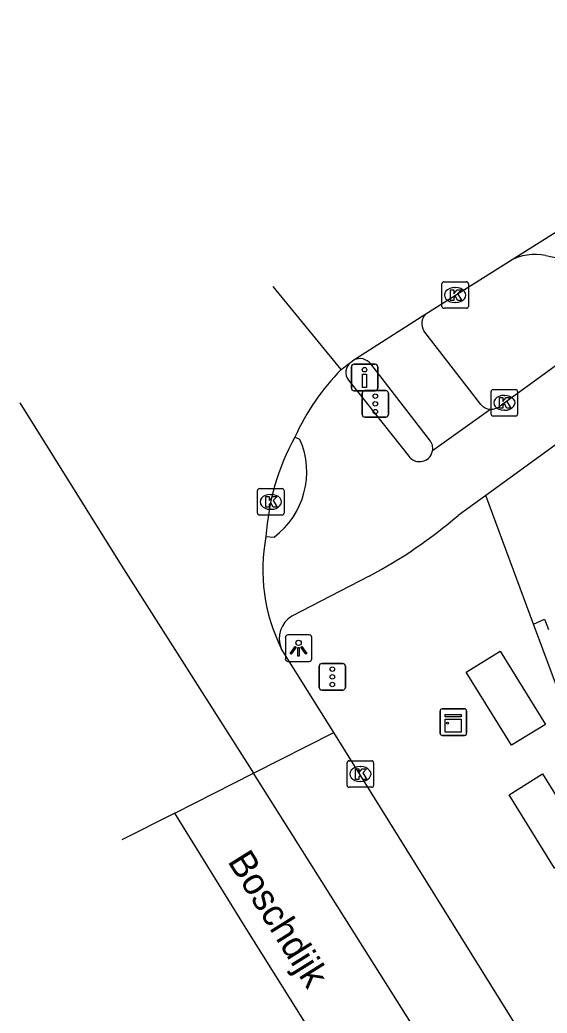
# Model space of a CAD drawing. Extents: x 160806 to 161707, y 383697 to 384148.
# Drawn here: x 160897.89 to 160917.75, y 383917.33 to 383954.76 of the extents above; entities that cross this region are included whole.
import ezdxf

# ---------------------------------------------------------------- set-up
doc = ezdxf.new("R2010")
doc.units = 0
for name, color, linetype in [('IMGEO_Drukknoppaal', 7, 'Continuous'), ('IMGEO_Fietspad_open', 7, 'Continuous'), ('IMGEO_Kast', 7, 'Continuous'), ('IMGEO_Kolk', 7, 'Continuous'), ('IMGEO_Lichtpunt', 7, 'Continuous'), ('IMGEO_Muur', 7, 'Continuous'), ('IMGEO_Openbare_ruimte_label', 7, 'Continuous'), ('IMGEO_Parkeervlak_open', 7, 'Continuous'), ('IMGEO_Rijbaan_lokaal_gesloten', 7, 'Continuous'), ('IMGEO_Rijbaan_lokaal_open', 7, 'Continuous'), ('IMGEO_Verkeersregelinstallatiepaal', 7, 'Continuous'), ('IMGEO_Voetpad_open', 7, 'Continuous')]:
    doc.layers.add(name, color=color, linetype=linetype)

msp = doc.modelspace()

# ---------------------------------------------------------------- linework, layer by layer
at = {"layer": 'IMGEO_Drukknoppaal'}
for p, q in [((160910.376, 383940.887), (160910.376, 383941.687)), ((160910.376, 383941.687), (160910.376, 383940.887)), ((160910.476, 383941.787), (160911.266, 383941.787)), ((160911.266, 383941.787), (160910.476, 383941.787)), ((160911.366, 383941.687), (160911.366, 383940.887)), ((160911.366, 383940.887), (160911.366, 383941.687)), ((160911.266, 383940.787), (160910.476, 383940.787)), ((160910.476, 383940.787), (160911.266, 383940.787))]:
    msp.add_line(p, q, dxfattribs=at)
msp.add_lwpolyline([(160910.946, 383941.412), (160910.946, 383940.912), (160910.796, 383940.912), (160910.796, 383941.412), (160910.946, 383941.412)], dxfattribs=at)
msp.add_circle((160910.871, 383941.577), 0.085, dxfattribs=at)
for centre, start, end in [((160910.476, 383941.687), 90, 180), ((160910.476, 383941.687), 90, 180), ((160911.266, 383941.687), 0, 90), ((160911.266, 383941.687), 360, 90), ((160910.476, 383940.887), 180, 270), ((160910.476, 383940.887), 180, 270), ((160911.266, 383940.887), 270, 0), ((160911.266, 383940.887), 270, 0)]:
    msp.add_arc(centre, 0.1, start, end, dxfattribs=at)
at = {"layer": 'IMGEO_Fietspad_open'}
for points in [[(160930.868, 383948.143), (160928.691, 383946.466), (160915.435, 383936.839)], [(160921.489, 383944.216), (160915.944, 383940.183)], [(160910.264, 383941.18), (160912.535, 383938.326)], [(160915.627, 383940.088), (160913.432, 383938.517)], [(160908.436, 383938.952), (160908.246, 383939.039)], [(160915.435, 383936.839), (160914.394, 383936.084)], [(160907.157, 383935.291), (160907.466, 383935.27)], [(160911.047, 383933.797), (160908.137, 383932.288)]]:
    msp.add_lwpolyline(points, dxfattribs=at)
for centre, radius, start, end in [((160910.656, 383941.475), 0.491, 128.8757, 216.9784), ((160915.641, 383940.616), 0.528, 268.4309, 304.9344), ((160905.618, 383937.726), 3.073, 306.9626, 23.5196), ((160912.945, 383938.61), 0.495, 313.4444, 349.2145), ((160912.943, 383938.609), 0.497, 214.7488, 313.6941), ((160902.215, 383950.316), 18.732, 298.1328, 310.5567), ((160908.632, 383931.451), 0.973, 120.6113, 202.7173)]:
    msp.add_arc(centre, radius, start, end, dxfattribs=at)
at = {"layer": 'IMGEO_Kast'}
for p, q in [((160913.79, 383928.797), (160914.631, 383928.797)), ((160914.631, 383928.797), (160913.79, 383928.797)), ((160913.715, 383927.872), (160913.715, 383928.713)), ((160913.715, 383928.713), (160913.715, 383927.872)), ((160914.715, 383928.722), (160914.715, 383927.881)), ((160914.715, 383927.881), (160914.715, 383928.722)), ((160914.64, 383927.797), (160913.799, 383927.797)), ((160913.799, 383927.797), (160914.64, 383927.797))]:
    msp.add_line(p, q, dxfattribs=at)
for points in [[(160913.91, 383928.587), (160914.51, 383928.587), (160914.51, 383928.502), (160913.91, 383928.502), (160913.91, 383928.587)], [(160913.91, 383928.412), (160914.51, 383928.412), (160914.51, 383927.923), (160913.91, 383927.923), (160913.91, 383928.412)]]:
    msp.add_lwpolyline(points, dxfattribs=at)
msp.add_circle((160913.994, 383928.261), 0.0377, dxfattribs=at)
for centre, start, end in [((160913.793, 383928.719), 92.4484, 184.2845), ((160913.793, 383928.719), 92.4484, 184.2845), ((160914.637, 383928.719), 2.4484, 94.2845), ((160914.637, 383928.719), 2.4484, 94.2845), ((160913.793, 383927.875), 182.4484, 274.2845), ((160913.793, 383927.875), 182.4484, 274.2845), ((160914.637, 383927.875), 272.4484, 4.2845), ((160914.637, 383927.875), 272.4484, 4.2845)]:
    msp.add_arc(centre, 0.0779, start, end, dxfattribs=at)
at = {"layer": 'IMGEO_Kolk'}
for p, q in [((160913.86, 383944.892), (160914.712, 383944.892)), ((160913.785, 383943.966), (160913.785, 383944.818)), ((160914.273, 383944.672), (160914.298, 383944.672)), ((160914.786, 383944.818), (160914.786, 383943.966)), ((160914.712, 383943.892), (160913.86, 383943.892)), ((160914.296, 383944.112), (160914.271, 383944.112)), ((160915.712, 383940.83), (160916.564, 383940.83)), ((160915.637, 383939.904), (160915.637, 383940.756)), ((160916.125, 383940.61), (160916.15, 383940.61)), ((160916.638, 383940.756), (160916.638, 383939.904)), ((160916.148, 383940.05), (160916.123, 383940.05)), ((160916.564, 383939.83), (160915.712, 383939.83)), ((160906.836, 383936.171), (160906.836, 383937.023)), ((160906.911, 383937.097), (160907.763, 383937.097)), ((160907.837, 383937.023), (160907.837, 383936.171)), ((160907.324, 383936.877), (160907.349, 383936.877)), ((160907.347, 383936.317), (160907.322, 383936.317)), ((160907.763, 383936.097), (160906.911, 383936.097)), ((160910.212, 383925.914), (160910.212, 383926.766)), ((160910.287, 383926.84), (160911.139, 383926.84)), ((160910.7, 383926.62), (160910.725, 383926.62)), ((160911.213, 383926.766), (160911.213, 383925.914)), ((160911.139, 383925.84), (160910.287, 383925.84)), ((160910.723, 383926.06), (160910.698, 383926.06))]:
    msp.add_line(p, q, dxfattribs=at)
for points in [[(160913.86, 383944.892), (160914.712, 383944.892)], [(160913.785, 383943.966), (160913.785, 383944.818)], [(160914.106, 383944.592), (160914.229, 383944.592), (160914.229, 383944.441), (160914.359, 383944.592), (160914.523, 383944.592), (160914.377, 383944.441), (160914.53, 383944.192), (160914.378, 383944.192), (160914.293, 383944.356), (160914.229, 383944.289), (160914.229, 383944.192), (160914.106, 383944.192), (160914.106, 383944.592)], [(160914.786, 383944.818), (160914.786, 383943.966)], [(160914.712, 383943.892), (160913.86, 383943.892)], [(160915.712, 383940.83), (160916.564, 383940.83)], [(160915.637, 383939.904), (160915.637, 383940.756)], [(160915.958, 383940.53), (160916.081, 383940.53), (160916.081, 383940.379), (160916.211, 383940.53), (160916.375, 383940.53), (160916.229, 383940.379), (160916.382, 383940.13), (160916.23, 383940.13), (160916.145, 383940.294), (160916.081, 383940.227), (160916.081, 383940.13), (160915.958, 383940.13), (160915.958, 383940.53)], [(160916.638, 383940.756), (160916.638, 383939.904)], [(160916.564, 383939.83), (160915.712, 383939.83)], [(160906.836, 383936.171), (160906.836, 383937.023)], [(160906.911, 383937.097), (160907.763, 383937.097)], [(160907.837, 383937.023), (160907.837, 383936.171)], [(160907.157, 383936.797), (160907.28, 383936.797), (160907.28, 383936.646), (160907.41, 383936.797), (160907.574, 383936.797), (160907.428, 383936.646), (160907.581, 383936.397), (160907.429, 383936.397), (160907.344, 383936.561), (160907.28, 383936.494), (160907.28, 383936.397), (160907.157, 383936.397), (160907.157, 383936.797)], [(160907.763, 383936.097), (160906.911, 383936.097)], [(160910.212, 383925.914), (160910.212, 383926.766)], [(160910.287, 383926.84), (160911.139, 383926.84)], [(160910.533, 383926.54), (160910.656, 383926.54), (160910.656, 383926.389), (160910.786, 383926.54), (160910.95, 383926.54), (160910.804, 383926.389), (160910.957, 383926.14), (160910.805, 383926.14), (160910.72, 383926.304), (160910.656, 383926.237), (160910.656, 383926.14), (160910.533, 383926.14), (160910.533, 383926.54)], [(160911.213, 383926.766), (160911.213, 383925.914)], [(160911.139, 383925.84), (160910.287, 383925.84)]]:
    msp.add_lwpolyline(points, dxfattribs=at)
for centre, start, end in [((160913.862, 383944.816), 91.552, 178.448), ((160913.862, 383944.816), 91.552, 178.448), ((160914.71, 383944.816), 1.552, 88.448), ((160914.71, 383944.816), 1.552, 88.448), ((160913.862, 383943.968), 181.552, 268.448), ((160913.862, 383943.968), 181.552, 268.448), ((160914.71, 383943.968), 271.552, 358.448), ((160914.71, 383943.968), 271.552, 358.448), ((160915.714, 383940.754), 91.552, 178.448), ((160915.714, 383940.754), 91.552, 178.448), ((160916.562, 383940.754), 1.552, 88.448), ((160916.562, 383940.754), 1.552, 88.448), ((160915.714, 383939.906), 181.552, 268.448), ((160915.714, 383939.906), 181.552, 268.448), ((160916.562, 383939.906), 271.552, 358.448), ((160916.562, 383939.906), 271.552, 358.448), ((160906.913, 383937.021), 91.552, 178.448), ((160906.913, 383937.021), 91.552, 178.448), ((160907.761, 383937.021), 1.552, 88.448), ((160907.761, 383937.021), 1.552, 88.448), ((160906.913, 383936.173), 181.552, 268.448), ((160906.913, 383936.173), 181.552, 268.448), ((160907.761, 383936.173), 271.552, 358.448), ((160907.761, 383936.173), 271.552, 358.448), ((160910.289, 383926.764), 91.552, 178.448), ((160910.289, 383926.764), 91.552, 178.448), ((160911.137, 383926.764), 1.552, 88.448), ((160911.137, 383926.764), 1.552, 88.448), ((160910.289, 383925.916), 181.552, 268.448), ((160910.289, 383925.916), 181.552, 268.448), ((160911.137, 383925.916), 271.552, 358.448), ((160911.137, 383925.916), 271.552, 358.448)]:
    msp.add_arc(centre, 0.0765, start, end, dxfattribs=at)
for centre, major_axis, ratio, start_param, end_param in [((160914.272, 383944.392), (-0.387, 0.002), 0.722429, 4.712389, 7.853982), ((160914.297, 383944.392), (-0.39, 0.002), 0.717154, 1.570796, 4.712389), ((160916.124, 383940.33), (-0.387, 0.002), 0.722429, 4.712389, 7.853982), ((160916.149, 383940.33), (-0.39, 0.002), 0.717154, 1.570796, 4.712389), ((160907.323, 383936.597), (-0.387, 0.002), 0.722429, 4.712389, 7.853982), ((160907.348, 383936.597), (-0.39, 0.002), 0.717154, 1.570796, 4.712389), ((160910.699, 383926.34), (-0.387, 0.002), 0.722429, 4.712389, 7.853982), ((160910.724, 383926.34), (-0.39, 0.002), 0.717154, 1.570796, 4.712389)]:
    msp.add_ellipse(centre, major_axis=major_axis, ratio=ratio, start_param=start_param, end_param=end_param, dxfattribs=at)
at = {"layer": 'IMGEO_Lichtpunt'}
for p, q in [((160907.887, 383931.487), (160907.887, 383930.68)), ((160907.887, 383931.487), (160907.887, 383930.68)), ((160908.789, 383931.582), (160907.981, 383931.582)), ((160908.789, 383931.582), (160907.981, 383931.582)), ((160908.883, 383930.68), (160908.883, 383931.487)), ((160908.883, 383930.68), (160908.883, 383931.487)), ((160907.981, 383930.586), (160908.789, 383930.586)), ((160907.981, 383930.586), (160908.789, 383930.586))]:
    msp.add_line(p, q, dxfattribs=at)
for points in [[(160908.261, 383931.151), (160908.3, 383931.123), (160908.112, 383930.861), (160908.074, 383930.888), (160908.261, 383931.151)], [(160908.363, 383931.103), (160908.41, 383931.103), (160908.41, 383930.781), (160908.363, 383930.781), (160908.363, 383931.103)], [(160908.473, 383931.123), (160908.511, 383931.15), (160908.698, 383930.888), (160908.659, 383930.86), (160908.473, 383931.123)]]:
    msp.add_lwpolyline(points, dxfattribs=at)
msp.add_circle((160908.386, 383931.285), 0.0994, dxfattribs=at)
for centre, start, end in [((160907.981, 383931.487), 90, 180), ((160907.981, 383931.487), 90, 180), ((160908.789, 383931.487), 0, 90), ((160908.789, 383931.487), 0, 90), ((160907.981, 383930.68), 180, 270), ((160907.981, 383930.68), 180, 270), ((160908.789, 383930.68), 270, 0), ((160908.789, 383930.68), 270, 360)]:
    msp.add_arc(centre, 0.0946, start, end, dxfattribs=at)
at = {"layer": 'IMGEO_Muur'}
for points in [[(160917.241, 383931.994), (160917.656, 383932.175), (160917.798, 383931.792)], [(160932.668, 383902.136), (160930.711, 383901.426), (160926.589, 383912.466), (160924.748, 383911.86), (160917.241, 383931.994)]]:
    msp.add_lwpolyline(points, dxfattribs=at)
at = {"layer": 'IMGEO_Parkeervlak_open'}
msp.add_lwpolyline([(160917.7, 383945.883), (160919.85, 383945.426)], dxfattribs=at)
msp.add_arc((160917.304, 383943.9), 2.022, 78.6939, 118.6913, dxfattribs=at)
at = {"layer": 'IMGEO_Rijbaan_lokaal_gesloten'}
for points in [[(160909.99, 383941.586), (160907.425, 383944.713)], [(160897.886, 383940.336), (160901.707, 383934.21), (160906.682, 383926.368)], [(160909.71, 383927.9), (160907.735, 383931.075)], [(160906.682, 383926.368), (160909.71, 383927.9)], [(160936.803, 383883.721), (160935.997, 383885.302), (160935.062, 383887.143), (160909.71, 383927.9)], [(160903.723, 383924.87), (160906.682, 383926.368)], [(160945.002, 383865.641), (160938.564, 383875.623), (160925.814, 383895.944), (160913.566, 383915.455), (160908.015, 383924.267), (160906.682, 383926.368)], [(160903.723, 383924.87), (160901.725, 383923.859)], [(160955.934, 383835.901), (160955.876, 383837.546), (160955.019, 383841.251), (160954.11, 383843.892), (160952.745, 383846.411), (160950.252, 383850.619), (160927.745, 383886.505), (160912.866, 383910.221), (160906.479, 383920.419), (160903.723, 383924.87)]]:
    msp.add_lwpolyline(points, dxfattribs=at)
for centre, radius, start, end in [((160916.234, 383935.44), 8.761, 135.4529, 155.7461), ((160916.102, 383934.724), 8.963, 151.2222, 176.3749), ((160913.674, 383934.037), 6.637, 169.108, 206.5048)]:
    msp.add_arc(centre, radius, start, end, dxfattribs=at)
at = {"layer": 'IMGEO_Rijbaan_lokaal_open'}
for points in [[(160916.333, 383945.674), (160930.784, 383954.763)], [(160913.178, 383943.681), (160916.333, 383945.674)], [(160910.466, 383941.945), (160913.178, 383943.681)], [(160910.348, 383941.857), (160910.466, 383941.945)], [(160909.99, 383941.586), (160910.348, 383941.857)]]:
    msp.add_lwpolyline(points, dxfattribs=at)
at = {"layer": 'IMGEO_Verkeersregelinstallatiepaal'}
for p, q in [((160910.881, 383940.789), (160911.671, 383940.789)), ((160911.671, 383940.789), (160910.881, 383940.789)), ((160910.781, 383939.889), (160910.781, 383940.689)), ((160910.781, 383940.689), (160910.781, 383939.889)), ((160911.771, 383940.689), (160911.771, 383939.889)), ((160911.771, 383939.889), (160911.771, 383940.689)), ((160911.671, 383939.789), (160910.881, 383939.789)), ((160910.881, 383939.789), (160911.671, 383939.789)), ((160909.161, 383929.605), (160909.161, 383930.405)), ((160909.161, 383930.405), (160909.161, 383929.605)), ((160909.261, 383930.505), (160910.051, 383930.505)), ((160910.051, 383930.505), (160909.261, 383930.505)), ((160910.151, 383930.405), (160910.151, 383929.605)), ((160910.151, 383929.605), (160910.151, 383930.405)), ((160910.051, 383929.505), (160909.261, 383929.505)), ((160909.261, 383929.505), (160910.051, 383929.505))]:
    msp.add_line(p, q, dxfattribs=at)
for centre in [(160911.276, 383940.579), (160911.276, 383940.289), (160911.276, 383939.999), (160909.656, 383930.295), (160909.656, 383930.005), (160909.656, 383929.715)]:
    msp.add_circle(centre, 0.085, dxfattribs=at)
for centre, start, end in [((160910.881, 383940.689), 90, 180), ((160910.881, 383940.689), 90, 180), ((160911.671, 383940.689), 0, 90), ((160911.671, 383940.689), 360, 90), ((160910.881, 383939.889), 180, 270), ((160910.881, 383939.889), 180, 270), ((160911.671, 383939.889), 270, 0), ((160911.671, 383939.889), 270, 0), ((160909.261, 383930.405), 90, 180), ((160909.261, 383930.405), 90, 180), ((160910.051, 383930.405), 0, 90), ((160910.051, 383930.405), 360, 90), ((160909.261, 383929.605), 180, 270), ((160909.261, 383929.605), 180, 270), ((160910.051, 383929.605), 270, 0), ((160910.051, 383929.605), 270, 0)]:
    msp.add_arc(centre, 0.1, start, end, dxfattribs=at)
at = {"layer": 'IMGEO_Voetpad_open'}
for points in [[(160915.249, 383940.272), (160913.107, 383943.045)], [(160913.323, 383938.932), (160911.109, 383941.796)], [(160917.241, 383931.994), (160915.435, 383936.839)], [(160914.701, 383930.178), (160915.977, 383930.968), (160917.684, 383928.212), (160916.408, 383927.422), (160914.701, 383930.178)], [(160916.317, 383925.562), (160917.576, 383926.342), (160919.293, 383923.57), (160918.033, 383922.79), (160916.317, 383925.562)]]:
    msp.add_lwpolyline(points, dxfattribs=at)
for centre, radius, start, end in [((160913.527, 383943.32), 0.502, 134.0183, 213.242), ((160910.694, 383941.468), 0.529, 38.351, 115.5556), ((160915.647, 383940.609), 0.521, 220.2524, 267.8365), ((160912.948, 383938.612), 0.493, 348.9258, 40.507)]:
    msp.add_arc(centre, radius, start, end, dxfattribs=at)

# ---------------------------------------------------------------- texts
at = {"layer": 'IMGEO_Openbare_ruimte_label'}
msp.add_text('Boschdijk', height=1, rotation=302.0054, dxfattribs=at).set_placement((160905.692, 383923.051))

doc.saveas('drawing.dxf')
